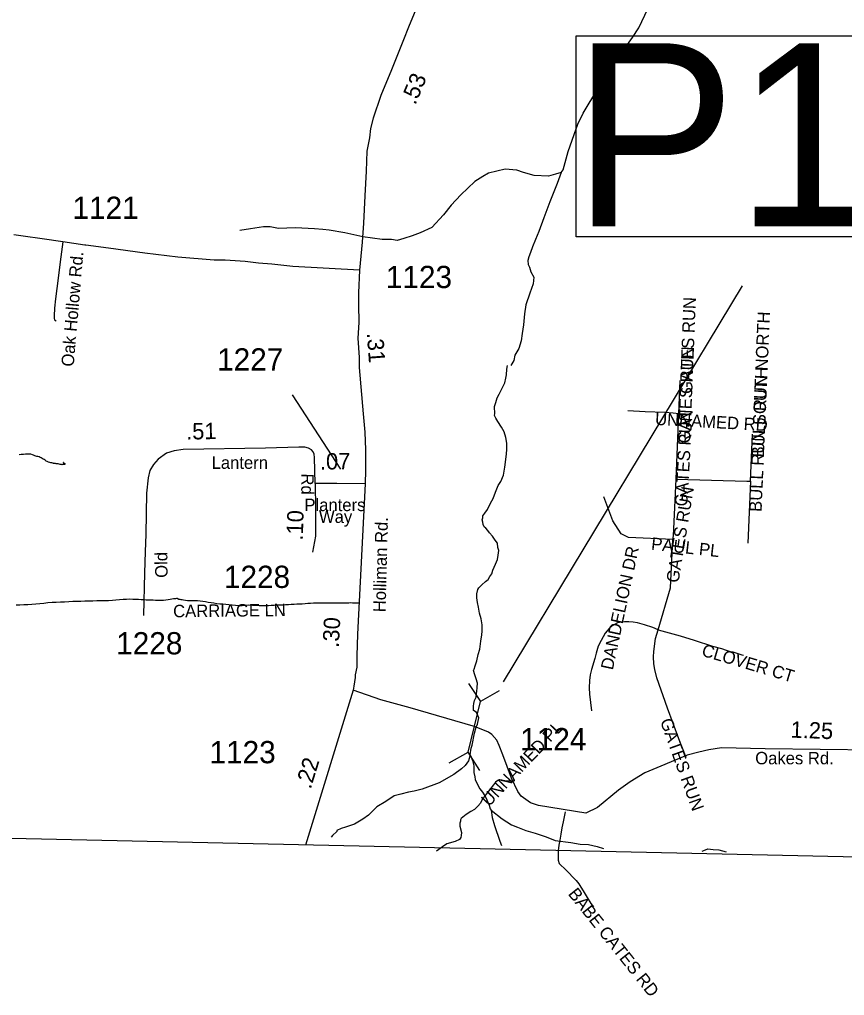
# Model space of a CAD drawing. Extents: x 1950930 to 2061844, y 904556 to 1017002.
# Drawn here: x 1999576 to 2005881, y 905144 to 912605 of the extents above; entities that cross this region are included whole.
import ezdxf

# ---------------------------------------------------------------- set-up
doc = ezdxf.new("R2010")
doc.units = 0
for name, color, linetype in [('Exist Boundary Political CountyLine', 7, 'Continuous'), ('Exist Hydrographic Creek Single Shore', 7, 'Continuous'), ('Exist Hydrographic Misc Water Feature', 7, 'Continuous'), ('Exist Road Non-System Type 51', 7, 'Continuous'), ('Exist Road Non-System Type 51 Label', 7, 'Continuous'), ('Exist Road Primary Interstate Structure Ovrhead Sign Attributed CELL', 7, 'Continuous'), ('Exist Road Primary US Structure Standard Bridge CELL', 7, 'Continuous'), ('Exist Road Secondary Structure Pipe Number Label', 7, 'Continuous'), ('Exist Road Secondary Type 51 Attributed', 7, 'Continuous'), ('Exist Road Secondary Type 51 Label', 7, 'Continuous'), ('Exist Road Secondary Type 51 Number Label', 7, 'Continuous')]:
    doc.layers.add(name, color=color, linetype=linetype)

msp = doc.modelspace()

# ---------------------------------------------------------------- linework, layer by layer
at = {"layer": 'Exist Boundary Political CountyLine'}
msp.add_lwpolyline([(2014538, 906012.8), (1997082.5, 906396.5), (1993199.8, 906445.3), (1978988.5, 906730.2), (1974332.2, 906819.9), (1966688.7, 906863.1), (1954666.9, 907077.7)], dxfattribs=at)
at = {"layer": 'Exist Hydrographic Creek Single Shore'}
msp.add_line((2003301.2, 909931.5), (2003305.2, 909959.4), dxfattribs=at)
for points in [[(2003715.8, 911433.9), (2003732, 911455.9), (2003769.6, 911595.9), (2003815.6, 911725.9), (2003843.5, 911804.1), (2003883.6, 911887.9), (2003995.5, 912075.9), (2004093.5, 912232.1), (2004135.3, 912300.1), (2004197.3, 912378.3), (2004261.2, 912468.2), (2004309.3, 912540.4), (2004377.3, 912686.3)], [(2003715.8, 911433.9), (2003671.9, 911423.6), (2003617.8, 911407.7), (2003509.9, 911411.6), (2003428, 911435.6), (2003375.8, 911451.7), (2003288, 911459.5), (2003159.8, 911429.3), (2003117.9, 911403.6), (2003056.1, 911365.5), (2002949.9, 911263.3), (2002874.1, 911185.1), (2002816.2, 911111.2), (2002728.2, 911015.2), (2002638.1, 910975), (2002576.3, 910951), (2002512.2, 910931), (2002462.3, 910915), (2002420.1, 910922.8), (2002348.3, 910922.9), (2002200.4, 910942.7), (2002062.2, 910974.8), (2001942.2, 910994.7), (2001894, 910998.6), (2001830.2, 911004.5), (2001686.3, 911012.4), (2001618.2, 911008.6), (2001556.2, 911006.2), (2001492.1, 911020.3), (2001440, 911020.4), (2001340.2, 911004.1), (2001260.2, 910992.3)], [(2003715.8, 911433.9), (2003683.9, 911351.9), (2003630.1, 911209.9), (2003584.2, 911087.8), (2003544.4, 910983.6), (2003518.2, 910923.7), (2003496.3, 910867.7), (2003482.3, 910823.7), (2003468.2, 910791.5), (2003460.4, 910763.5), (2003462.4, 910731.6), (2003472.5, 910711.7), (2003484.5, 910675.7), (2003506.3, 910635.5), (2003500.3, 910583.5), (2003476.5, 910511.8), (2003444.5, 910423.5), (2003434.6, 910355.4), (2003426.6, 910269.6), (2003416.7, 910203.5), (2003408.6, 910147.6), (2003392.7, 910089.5), (2003362.7, 910037.6), (2003352.7, 909997.4), (2003330.9, 909959.5)], [(2003019, 906983.4), (2003028.8, 907034.3), (2003035.1, 907058), (2003040.3, 907084.1), (2003048.4, 907124.1), (2003054.1, 907148.1), (2003066.7, 907194), (2003076.2, 907217.7), (2003085.7, 907265.2), (2003079.4, 907284.1), (2003068.3, 907306.3), (2003057.3, 907315.8), (2003044.8, 907323.3), (2003044.7, 907355.3), (2003048.7, 907375.4), (2003052.8, 907399.3), (2003064.7, 907423.3), (2003068.7, 907451.4), (2003070.6, 907467.4), (2003074.6, 907499.3), (2003076.7, 907531.5), (2003066.6, 907563.3), (2003054.6, 907595.3), (2003046.5, 907627.3), (2003050.5, 907639.4), (2003058.6, 907663.3), (2003070.5, 907703.4), (2003082.5, 907751.4), (2003094.5, 907791.4), (2003100.5, 907851.4), (2003108.3, 907901.5), (2003112.3, 907929.4), (2003112.3, 907977.4), (2003104.3, 908023.4), (2003092.4, 908067.5), (2003084.3, 908111.4), (2003076.2, 908147.4), (2003072.2, 908183.3), (2003070.2, 908215.3), (2003078.3, 908247.4), (2003086.1, 908259.4), (2003110.2, 908283.3), (2003138.1, 908307.4), (2003158.1, 908323.4), (2003170.2, 908347.5), (2003186.2, 908367.4), (2003194.1, 908395.4), (2003214.1, 908441.4), (2003230, 908477.5), (2003234.1, 908509.4), (2003238.1, 908545.5), (2003231.9, 908569.5), (2003228, 908601.4), (2003211.9, 908625.5), (2003191.9, 908655.5), (2003168, 908679.4), (2003156, 908699.5), (2003139.9, 908715.4), (2003127.9, 908725.5), (2003120, 908745.4), (2003115.9, 908763.3), (2003111.9, 908779.4), (2003115.8, 908795.3), (2003115.9, 908811.3), (2003131.9, 908831.4), (2003151.9, 908859.4), (2003175.7, 908907.5), (2003195.8, 908943.5), (2003213.6, 908991.5), (2003233.7, 909041.5), (2003253.7, 909073.5), (2003273.7, 909121.5), (2003285.6, 909181.5), (2003293.6, 909241.5), (2003297.5, 909285.5), (2003299.6, 909317.4), (2003299.6, 909365.4), (2003291.5, 909409.4), (2003279.4, 909453.5), (2003259.5, 909489.5), (2003231.4, 909531.5), (2003215.3, 909557.4), (2003207.3, 909577.4), (2003207.5, 909593.4), (2003207.4, 909609.4), (2003207.3, 909625.4), (2003207.3, 909645.4), (2003215.4, 909677.4), (2003225.3, 909711.4), (2003241.3, 909741.5), (2003257.3, 909771.4), (2003265.3, 909787.4), (2003269.2, 909795.5), (2003285.3, 909827.4), (2003293.2, 909863.5), (2003297.1, 909887.4), (2003301.2, 909931.5)], [(2003019, 906983.4), (2003007.1, 906937.4), (2002982.9, 906903.3), (2002955, 906875.3), (2002895.1, 906833.3), (2002783.1, 906769.2), (2002653.1, 906721.1), (2002593.2, 906705.1), (2002549.2, 906697), (2002491.1, 906683), (2002439.2, 906669), (2002375.1, 906627), (2002307.3, 906586.9), (2002243.2, 906522.9), (2002199.3, 906490.8), (2002135.3, 906452.9), (2002067.2, 906430.9), (2002035.4, 906420.7), (2002001.3, 906404.8), (2002001.3, 906396.8), (2001969.3, 906366.7), (2001957.9, 906355.2)]]:
    msp.add_lwpolyline(points, dxfattribs=at)
at = {"layer": 'Exist Hydrographic Misc Water Feature'}
for points in [[(2003019, 906983.4), (2003038.9, 906939.3), (2003043.1, 906919.5), (2003047.1, 906899.4), (2003047.1, 906879.4), (2003047, 906847.4), (2003055.1, 906815.4), (2003059.1, 906795.3), (2003071.2, 906767.4), (2003095.1, 906723.3), (2003113.2, 906699.4), (2003133.2, 906671.3), (2003145.1, 906647.5), (2003153.1, 906627.5), (2003165.1, 906599.5), (2003173.1, 906571.5), (2003181.3, 906559.5)], [(2003181.3, 906559.5), (2003265.2, 906495.6), (2003337.2, 906449.5), (2003381.3, 906431.6), (2003445.4, 906405.7), (2003517.4, 906385.6), (2003601.4, 906357.6), (2003669.2, 906329.8), (2003789.3, 906313.8), (2003861.3, 906301.9), (2003925.4, 906298), (2003991.3, 906282), (2004040.2, 906268.3)], [(2003181.3, 906559.5), (2003189.2, 906505.6), (2003205.3, 906443.4), (2003247.4, 906323.5), (2003260.3, 906289.4)], [(2004793.7, 906248), (2004805.2, 906252.4), (2004837.3, 906264.6), (2004877.4, 906260.5), (2004921.3, 906256.6), (2004975.8, 906243)]]:
    msp.add_lwpolyline(points, dxfattribs=at)
at = {"layer": 'Exist Road Non-System Type 51'}
for p, q in [((2004615.5, 909590.9), (2004625.6, 909845.4)), ((2004595.5, 909090.4), (2004615.5, 909590.9)), ((2005162.1, 909075.9), (2005177.4, 909436.1))]:
    msp.add_line(p, q, dxfattribs=at)
for points in [[(1999907.9, 910904.9), (1999886.4, 910751.2), (1999869, 910608), (1999861.1, 910547.1), (1999851.2, 910468.1), (1999844.1, 910398.4), (1999840.1, 910339.9), (1999840.5, 910317.8), (1999844.5, 910309.1), (1999855.6, 910301.2)], [(2004615.5, 909590.9), (2004570.2, 909596.3), (2004508.4, 909600.4), (2004356.6, 909605.8), (2004224, 909612.9)], [(1999913, 909219.5), (1999912, 909218.2), (1999911, 909217.1), (1999911, 909215.9), (1999913.5, 909215.2), (1999917.4, 909214), (1999920.9, 909212.2), (1999922.9, 909210.4), (1999923.4, 909208.6), (1999922.9, 909207.4), (1999922.4, 909206.8), (1999922.9, 909206.1), (1999923.9, 909206.1), (1999924.4, 909205.6), (1999924.8, 909205.6), (1999925.2, 909205.6), (1999924.4, 909204.9), (1999921.9, 909204.3), (1999918.9, 909203.7), (1999914.5, 909202.5), (1999910, 909201.9), (1999905.6, 909201.9), (1999901.8, 909201.3), (1999897.2, 909201.9), (1999892.4, 909202.5), (1999886.5, 909203.7), (1999879.1, 909205.6), (1999871.2, 909206.8), (1999864.4, 909207.9), (1999857.5, 909209.2), (1999850.6, 909209.8), (1999844.8, 909211), (1999840.8, 909211.6), (1999838.2, 909211.6), (1999836.9, 909211.6), (1999835.9, 909211.6), (1999833.9, 909212.2), (1999830, 909212.8), (1999824, 909214.6), (1999816.2, 909216.4), (1999807.4, 909218.9), (1999798, 909221.9), (1999788.1, 909224.9), (1999780.2, 909229.2), (1999773, 909235.2), (1999764.6, 909240.1), (1999756.8, 909245), (1999748.9, 909249.2), (1999740.5, 909253.5), (1999733.1, 909257.7), (1999725.2, 909260.8), (1999717.4, 909263.2), (1999709.5, 909265), (1999701.1, 909267.4), (1999692.9, 909269.9), (1999683.5, 909273.5), (1999674.6, 909277.1), (1999663.9, 909280.8), (1999651, 909282), (1999636.8, 909282), (1999621.1, 909281.4), (1999605.4, 909280.2), (1999589.6, 909278.4), (1999573.9, 909275.9)], [(2004569.6, 908629.2), (2004574.6, 908657.2), (2004595.5, 909090.4)], [(2004595.5, 909090.4), (2005135, 909075.9), (2005162.1, 909075.9)], [(2005162.1, 909075.9), (2005142.1, 908602.7), (2005142.1, 908602.7)], [(2004569.6, 908629.2), (2004231, 908645.1), (2004174.5, 908673.3), (2004111, 908772.2), (2004040.8, 908955.9)], [(2004457.8, 907938.1), (2004552.2, 908258.9), (2004569.6, 908629.2)], [(1999551.2, 908129.1), (1999579.8, 908130.9), (1999608.8, 908132.8), (1999638.8, 908134), (1999669.2, 908135.8), (1999700.1, 908138.2), (1999731.1, 908141.2), (1999762.1, 908143.7), (1999793.6, 908147.3), (1999825, 908149.8), (1999857, 908151), (1999888.9, 908152.2), (1999920.4, 908154), (1999951.9, 908155.8), (1999982.8, 908157.1), (2000013.8, 908158.9), (2000044.8, 908159.4), (2000075.2, 908160.1), (2000105.6, 908161.3), (2000136.1, 908161.9), (2000166.6, 908162.5), (2000196.6, 908163.1), (2000227.1, 908163.1), (2000256.6, 908163.7), (2000285.6, 908164.9), (2000313.1, 908167.9), (2000340.6, 908171.6), (2000367.6, 908172.8), (2000392.8, 908174), (2000417.2, 908175.2), (2000441.4, 908174.6), (2000464, 908173.4), (2000486.1, 908172.8), (2000506.2, 908171.6), (2000525.9, 908170.4), (2000544.1, 908168.6), (2000561.2, 908168.6), (2000578.5, 908168.6), (2000596.6, 908167.4), (2000615.9, 908166.8), (2000636, 908166.1), (2000656.1, 908164.9), (2000675.9, 908166.1), (2000694.5, 908167.9), (2000712.1, 908169.8), (2000727.4, 908172.8), (2000740.8, 908175.9), (2000752.5, 908177.7), (2000762.8, 908178.9), (2000771.1, 908178.9), (2000777.5, 908180.1), (2000782, 908180.7), (2000784, 908180.1), (2000784.4, 908178.9), (2000784.9, 908177.7), (2000784.9, 908175.9), (2000786.9, 908175.2), (2000790.4, 908174.1), (2000795.2, 908173.4), (2000801.1, 908172.8), (2000809.5, 908171.6), (2000818.9, 908169.8), (2000830.6, 908168), (2000844.4, 908166.1), (2000861.1, 908164.3), (2000878.4, 908164.3), (2000896.5, 908164.3), (2000915.6, 908163.8), (2000935.4, 908163.1), (2000955.5, 908161.3), (2000976.1, 908159.5), (2000996.8, 908155.2), (2001018.9, 908150.4), (2001040.5, 908146.8), (2001062.1, 908144.3), (2001084.2, 908141.2), (2001106.9, 908138.9), (2001129.5, 908137.1), (2001152.1, 908135.2), (2001176.1, 908132.8), (2001201.2, 908129.8), (2001226.8, 908126.8), (2001252.4, 908125.5), (2001278.4, 908125.5), (2001303.5, 908127.3), (2001329.5, 908129.1)], [(2001329.5, 908129.1), (2001355.6, 908128.6), (2001381.1, 908127.3), (2001406.6, 908126.1), (2001431.2, 908124.9), (2001454.9, 908124.9), (2001478, 908126.1), (2001500.5, 908126.8), (2001522.6, 908127.4), (2001543.8, 908129.2), (2001565.4, 908129.8), (2001587.5, 908129.8), (2001609.6, 908131.6), (2001631.2, 908133.4), (2001652.9, 908134.6), (2001674, 908135.9), (2001694.8, 908137.1), (2001715.9, 908137.7), (2001737, 908138.9), (2001758.1, 908140.7), (2001779.2, 908141.9), (2001800.9, 908143.1), (2001822.5, 908144.4), (2001844.6, 908144.9), (2001866.8, 908145.6), (2001889.4, 908146.2), (2001912, 908146.2), (2001934, 908146.2), (2001956.1, 908145.6), (2001977.8, 908145.6), (2001998.5, 908145.6), (2002018.6, 908145.6), (2002038.2, 908145.6), (2002057.4, 908145.6), (2002075.6, 908146.2), (2002092.4, 908146.2), (2002108, 908146.8), (2002121.8, 908146.2), (2002134.1, 908146.2), (2002144.9, 908146.2), (2002154.2, 908146.2), (2002161.1, 908145.6), (2002165.1, 908145), (2002166.5, 908145), (2002167, 908145), (2002166.5, 908145)], [(2004457.8, 907938.1), (2004415, 907956.9), (2004353.4, 907977.2), (2004298, 907993.8), (2004264.9, 907998.4), (2004233.5, 908001.1), (2004199.5, 908001.1), (2004178.2, 907997.4), (2004145.1, 907991.9), (2004105.5, 907970.8), (2004081.5, 907949.6), (2004053, 907912.7), (2004020.8, 907857.4), (2003999.5, 907815), (2003982, 907759.8), (2003971.9, 907721.1), (2003947.5, 907635.4), (2003938.2, 907593.9), (2003932.8, 907551.6), (2003929.1, 907496.2), (2003931.9, 907447.4), (2003947, 907320.3)], [(2004670.9, 906964.2), (2004614.8, 907104.7), (2004528.8, 907340.4), (2004445.8, 907571.7), (2004430.4, 907634.8), (2004424.4, 907679.8), (2004421.4, 907733.1), (2004422.9, 907772.9), (2004437.5, 907872), (2004457.8, 907938.1)], [(2004457.8, 907938.1), (2004624.5, 907893), (2004731.1, 907859.9), (2004872.2, 907814.9), (2004941.2, 907795.4), (2004977.4, 907783.4), (2005005.9, 907774.4), (2005026.9, 907769.9), (2005065.9, 907759.4), (2005097, 907749.1), (2005109.4, 907744.8)], [(2003361.2, 906784.9), (2003329.4, 906783), (2003284.9, 906784.9), (2003261.2, 906789.2), (2003240.9, 906792.1), (2003230.8, 906788.5), (2003214.6, 906774.3), (2003199.4, 906753.2), (2003171.4, 906719.3), (2003141.9, 906682.6), (2003113, 906642.1), (2003098.2, 906613.1), (2003078.9, 906590.3), (2003053.4, 906566.4), (2003024.4, 906549.4), (2002990.2, 906527.2), (2002965.1, 906507.9), (2002950.4, 906496.5), (2002946.4, 906486.8), (2002945.2, 906476.6), (2002942.4, 906461.2), (2002941.2, 906439.1), (2002953.2, 906389), (2002952.6, 906367.2), (2002949.2, 906350.6), (2002938.2, 906337.2), (2002906, 906320.6), (2002841.6, 906302.8), (2002808.2, 906279.4), (2002762.8, 906247.2)], [(2003745.2, 906547.1), (2003739.4, 906510.4), (2003731.5, 906471), (2003721.6, 906426.3), (2003711.8, 906376.2), (2003704.8, 906331.3), (2003700.1, 906306.9), (2003698.4, 906291.8), (2003693.1, 906249.2), (2003691.4, 906212.5), (2003693.1, 906179.3), (2003699.5, 906152.5), (2003714, 906139.1), (2003740.2, 906114.6), (2003774, 906081.4), (2003805.5, 906048.8), (2003829.4, 906022), (2003849.8, 905997), (2003866.6, 905971.9), (2003884.8, 905943.4), (2003913.2, 905892.7), (2003941.9, 905846.7), (2003962.2, 905822.2)]]:
    msp.add_lwpolyline(points, dxfattribs=at)
at = {"layer": 'Exist Road Primary Interstate Structure Ovrhead Sign Attributed CELL'}
for p, q in [((2003007.5, 907530.1), (2003098.1, 907390.3)), ((2003242.6, 907473.2), (2003098.1, 907390.3)), ((2003004.7, 907004.7), (2003098.1, 907390.3)), ((2002860.2, 906921.9), (2003004.7, 907004.7)), ((2003095.2, 906865), (2003004.7, 907004.7))]:
    msp.add_line(p, q, dxfattribs=at)
at = {"layer": 'Exist Road Secondary Structure Pipe Number Label'}
msp.add_line((2003273.8, 907542.1), (2005101.8, 910569.8), dxfattribs=at)
msp.add_lwpolyline([(2003830.6, 912479.2), (2008895.2, 912479.2), (2008895.2, 910943.8), (2003830.6, 910943.8)], close=True, dxfattribs=at)
at = {"layer": 'Exist Road Secondary Type 51 Attributed'}
msp.add_line((2002126, 907476.9), (2001760.9, 906293.7), dxfattribs=at)
for points in [[(2002899.3, 913329.8), (2002864, 913255.7), (2002768.4, 913068.8), (2002695.5, 912897.1), (2002626.4, 912730.7), (2002553.6, 912559), (2002505, 912435.9), (2002419.2, 912219.4), (2002337.2, 912023.9), (2002278.8, 911850.9), (2002259, 911771.9), (2002249.9, 911699), (2002231.7, 911597.2), (2002224.9, 911444.5), (2002214.2, 911256.1), (2002204.3, 911046.9), (2002194.6, 910902.8), (2002174.4, 910688.2)], [(2002174.4, 910688.2), (2001665.8, 910715.5), (2001505.6, 910733.9), (2001401.6, 910742.9), (2001301.4, 910755), (2001146.6, 910764.1), (2001063.9, 910765.1), (2000785.3, 910788.4), (2000533.2, 910818.8), (2000256.2, 910856.1), (2000082.3, 910880.4), (2000076.3, 910880.3), (1999907.8, 910904.9), (1999750.2, 910929.3), (1999605.2, 910947.4), (1999533.8, 910957.6)], [(2002174.4, 910688.2), (2002166.2, 910515.9), (2002166.1, 910423.9), (2002168.3, 910287.8), (2002161.5, 910167.7), (2002172.1, 910021.9), (2002172.1, 909944.4), (2002201.7, 909589.8), (2002213.9, 909450.9), (2002219, 909316.1), (2002220.1, 909260), (2002220.8, 909160.2), (2002218.5, 909054.7)], [(2001836.2, 909056.7), (2001829.9, 909257.7), (2001826.7, 909280.9), (2001820.4, 909298.8), (2001807.7, 909314.7), (2001785.6, 909328.4), (2001756, 909334.7), (2001711.7, 909335.7), (2001455.9, 909327.3), (2000826.4, 909317.1), (2000757.3, 909307.7), (2000700.7, 909288.9), (2000634.7, 909244.9), (2000600.1, 909204), (2000571.8, 909156.9), (2000559.2, 909100.4), (2000546.7, 908984.1), (2000540.4, 908669.9), (2000537.2, 908534.8), (2000530.9, 908374.6), (2000523.7, 908047.8)], [(2001836.2, 909056.7), (2001837.3, 908864.8), (2001837.1, 908677.8), (2001838.3, 908653.9), (2001814.9, 908531.7)], [(2002218.5, 909054.7), (2002000.3, 909057.8), (2001836.2, 909056.7)], [(2002218.5, 909054.7), (2002160.1, 907905.4), (2002154.4, 907739.6), (2002152.8, 907653.8), (2002141.2, 907594.4), (2002141.6, 907575.9), (2002136.7, 907541.2), (2002131.7, 907507.4), (2002126, 907476.9)], [(2003066.7, 907194), (2003042.2, 907201.7), (2002562.5, 907342), (2002336.5, 907404.8), (2002126, 907476.9)], [(2006114.2, 907018.8), (2005274.1, 907030.5), (2004939.9, 907036.6), (2004843.2, 907022.7), (2004768.7, 907003.8), (2004678.1, 906981.9), (2004355.8, 906846.6), (2004244.1, 906776.8), (2004154.6, 906713.7), (2003993.9, 906580.1), (2003902.8, 906536.8), (2003542.2, 906595.7), (2003480.3, 906617.2), (2003411.1, 906667.5), (2003385.1, 906703.4), (2003335, 906805.6), (2003271, 906983.6), (2003242.9, 907055.6), (2003225, 907095.5), (2003186.5, 907139.9), (2003161, 907156), (2003066.7, 907194)]]:
    msp.add_lwpolyline(points, dxfattribs=at)
at = {"layer": 'Exist Road Secondary Type 51 Number Label'}
msp.add_line((2002031, 909168), (2001662.5, 909736.1), dxfattribs=at)

# ---------------------------------------------------------------- texts
at = {"layer": 'Exist Road Non-System Type 51 Label'}
for s, rotation, p in [('Oak Hollow Rd.', 85.08582, (1999989.5, 909948.3)), ('  GATES RUN', 87.74321, (2004713.8, 909670)), ('  BULL RUN NORTH', 87.56335, (2005261.9, 909185.8)), ('  GATES RUN', 87.74321, (2004698.6, 909292.5)), ('  BULL RUN SOUTH', 87.57708, (2005244.3, 908768.8)), ('  UNNAMED RD', 356.78301, (2004361, 909510.1)), ('  GATES RUN', 86.77548, (2004675, 908810.1)), ('  GATES RUN', 80.77608, (2004600.3, 908224.6)), ('  PAUL PL', 353.62874, (2004329.8, 908560.4)), ('  DANDELION DR', 77.93327, (2004095.1, 907558.4)), ('  CARRIAGE LN', 0.62502, (2000680.1, 908033.9)), ('  CLOVER CT', 343.46765, (2004715.2, 907762.6)), ('  UNNAMED PL', 46.44495, (2003115.8, 906532.5)), ('  GATES RUN', 289.72156, (2004446.2, 907309.2)), ('  BABE CATES RD', 308.50821, (2003719.7, 905974.4))]:
    msp.add_text(s, height=95, rotation=rotation, dxfattribs=at).set_placement(p)
at = {"layer": 'Exist Road Primary US Structure Standard Bridge CELL'}
for s, rotation, p in [('.53', 67.25011, (2002600.9, 911946)), ('.31', 274.16698, (2002230.2, 910207.6)), ('.51', 0.92432, (2000850.5, 909393.7)), ('.07', 0.38652, (2001872.3, 909164.5)), ('.10', 88.12796, (2001740.6, 908619.6)), ('.30', 87.09508, (2002016.4, 907800.5)), ('1.25', 357.77044, (2005466.7, 907115.5)), ('.22', 72.73064, (2001800.7, 906716.3))]:
    msp.add_text(s, height=125, rotation=rotation, dxfattribs=at).set_placement(p)
at = {"layer": 'Exist Road Secondary Structure Pipe Number Label'}
msp.add_text('P125', height=1400, dxfattribs=at).set_placement((2003802.2, 911022.9))
at = {"layer": 'Exist Road Secondary Type 51 Label'}
for s, p in [('Lantern', (2001044.2, 909169.8)), ('Planters', (2001753.5, 908846.6)), ('Way', (2001864.7, 908756.5)), ('Oakes Rd.', (2005198.4, 906911.1))]:
    msp.add_text(s, height=95, dxfattribs=at).set_placement(p)
for s, rotation, p in [('Rd', 269.55943, (2001730.5, 909134.7)), ('Holliman Rd.', 88.56898, (2002373.8, 908072.7)), ('Old', 90.68575, (2000708.3, 908337))]:
    msp.add_text(s, height=95, rotation=rotation, dxfattribs=at).set_placement(p)
at = {"layer": 'Exist Road Secondary Type 51 Number Label'}
for s, p in [('1121', (1999980.8, 911080.4)), ('1123', (2002375.8, 910551.6)), ('1227', (2001086.3, 909921.2)), ('1228', (2001138.5, 908259.4)), ('1228', (2000315.2, 907751.5)), ('1124', (2003402.5, 907018.4)), ('1123', (2001028.2, 906919.2))]:
    msp.add_text(s, height=170, dxfattribs=at).set_placement(p)

doc.saveas('drawing.dxf')
